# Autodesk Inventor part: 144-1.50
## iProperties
Created: 2007-06
Part Number: 144-1.50
Document SubType Name: Modeling
Designer: btaylor
Density: 1 g/cm^3
Author: btaylor
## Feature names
1. Extrusion1
2. Extrusion2
3. Extrusion3
4. Extrusion4
5. Extrusion5
6. Chamfer1
7. Chamfer2
8. Fillet1
9. Fillet2
